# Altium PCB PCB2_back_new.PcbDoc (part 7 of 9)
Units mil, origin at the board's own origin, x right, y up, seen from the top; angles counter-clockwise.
Board outline 6299 x 3937 mil, 4 copper layers (TopLayer, GROUND, VCC, BottomLayer); 253 components, 421 nets, 2085 pads, 712 vias.
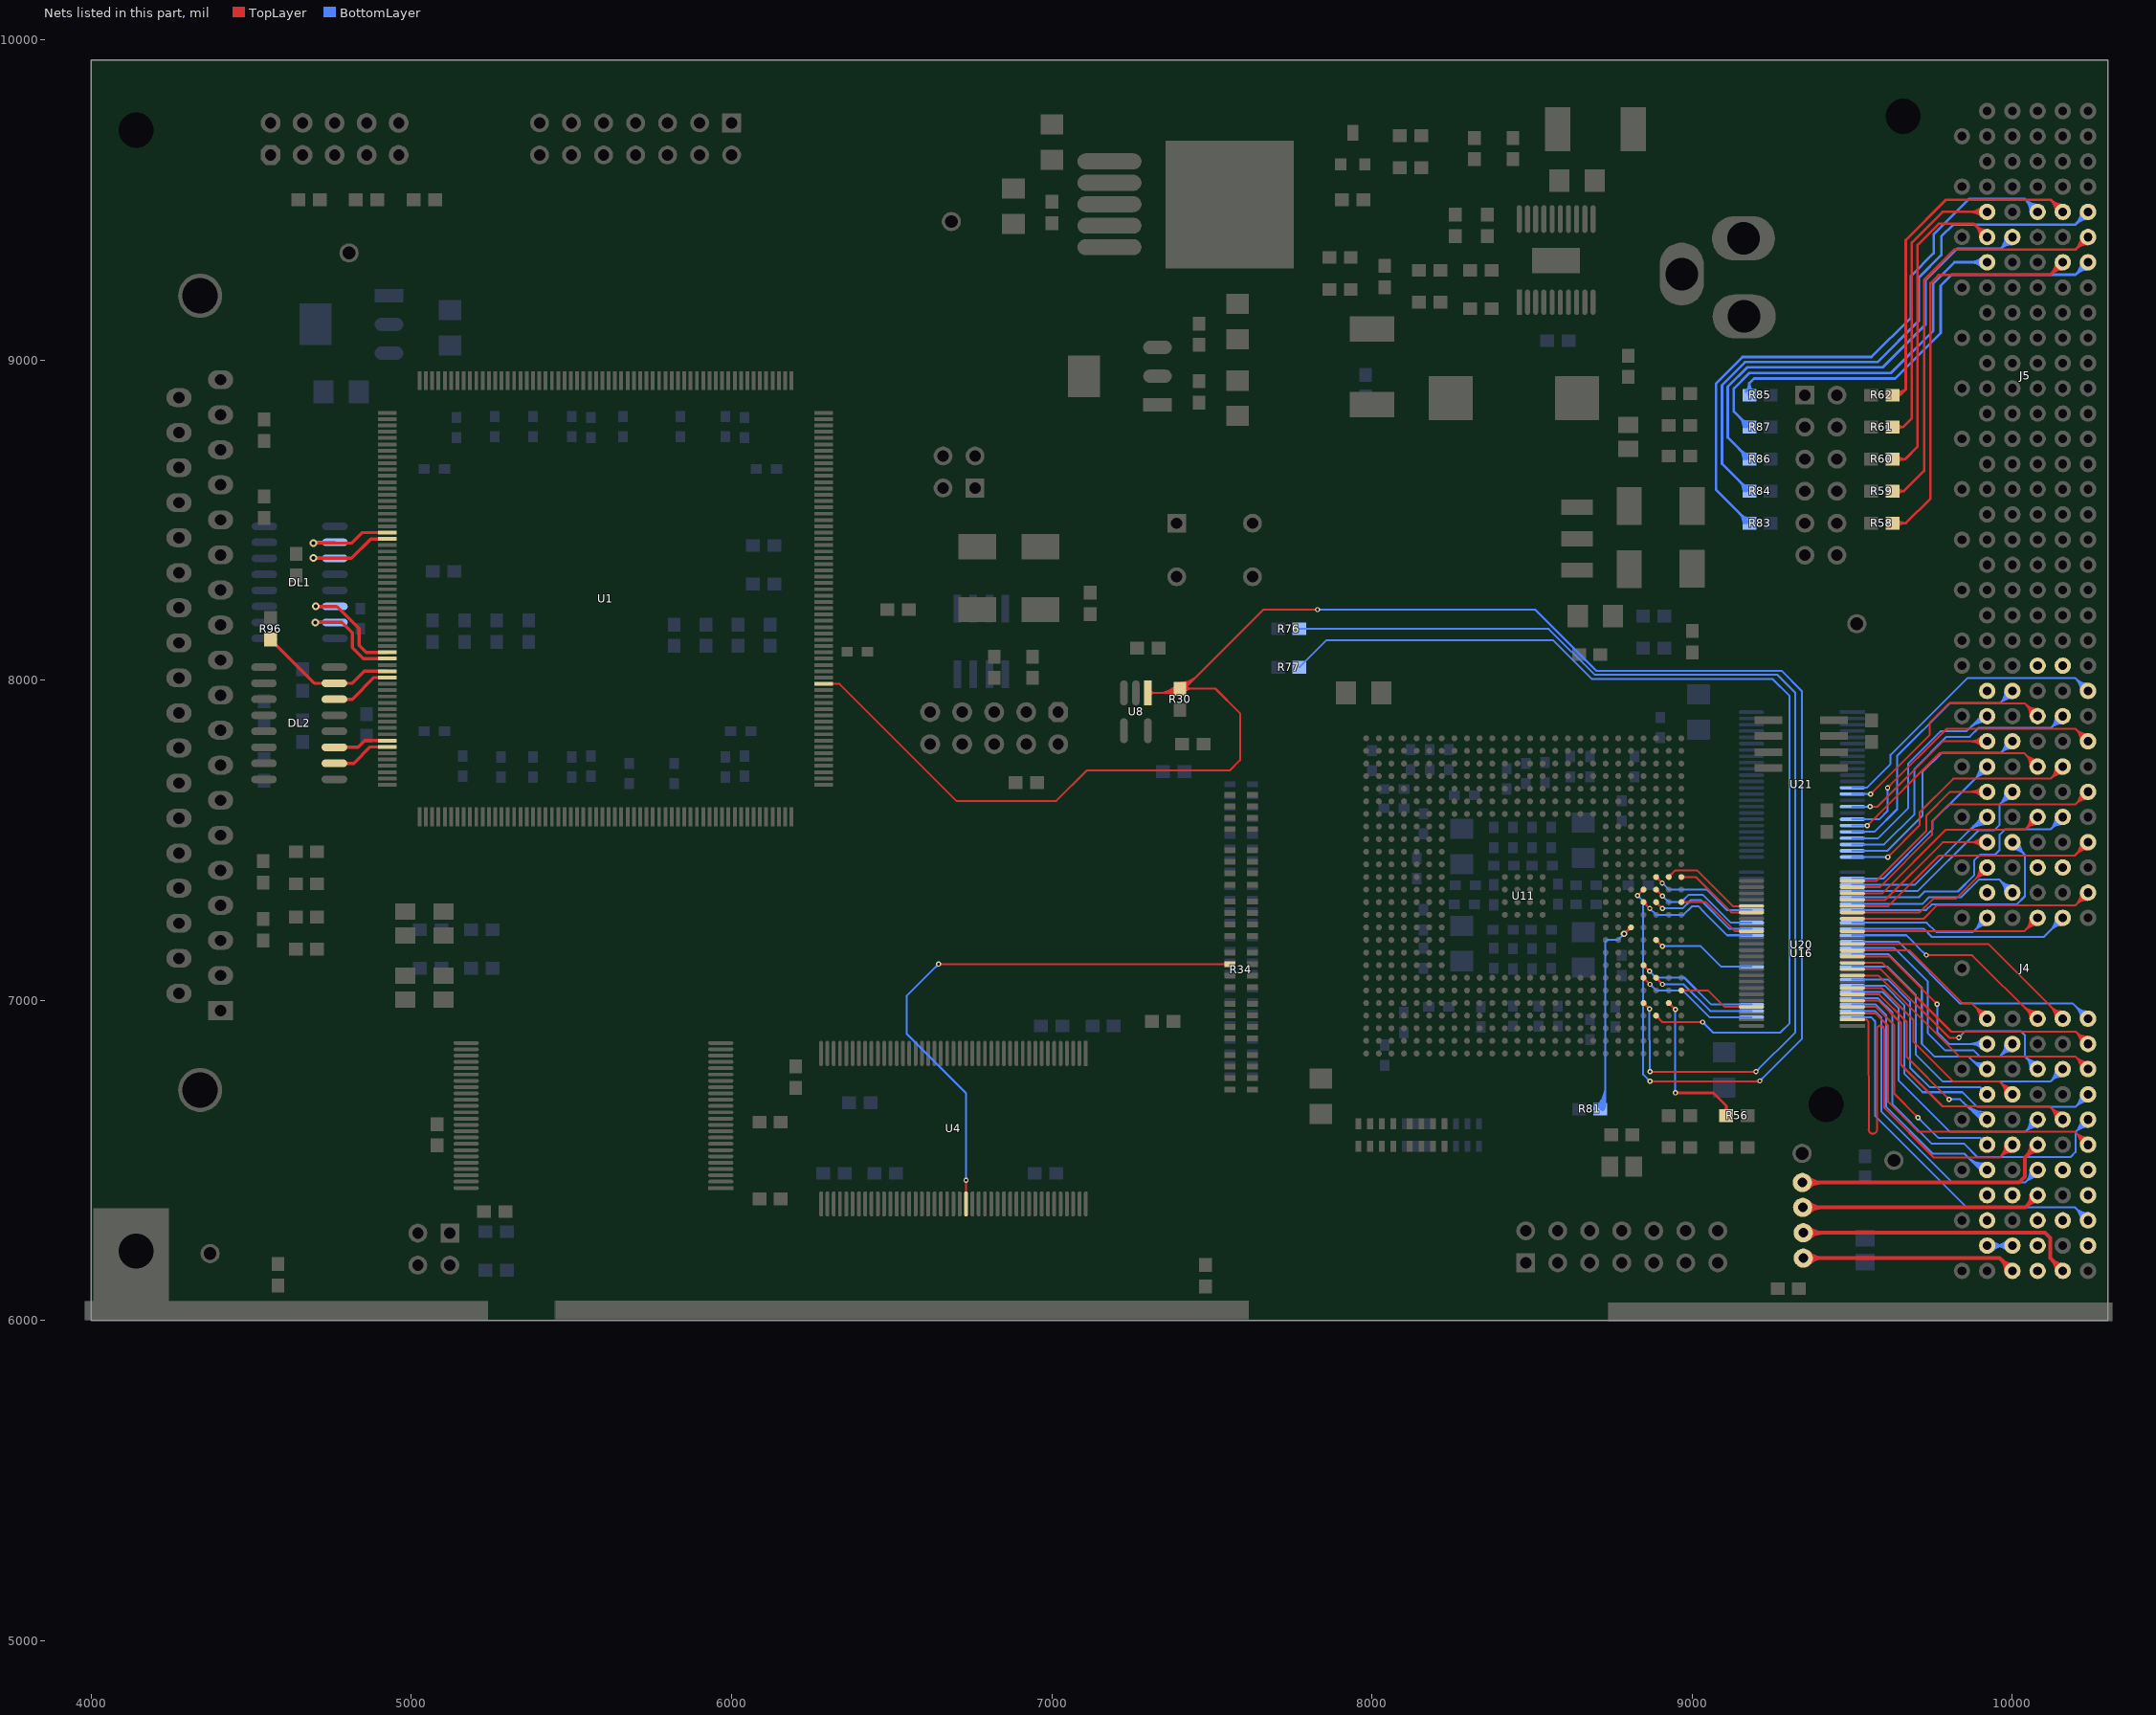
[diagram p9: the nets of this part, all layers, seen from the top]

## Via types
v1: diameter 16, hole 8, TopLayer to BottomLayer, 311 vias
v2: diameter 20, hole 10, TopLayer to BottomLayer, 202 vias
v3: diameter 24, hole 12, TopLayer to BottomLayer, 179 vias
v4: diameter 40, hole 20, TopLayer to BottomLayer, 12 vias
v5: diameter 30, hole 15, TopLayer to BottomLayer, 8 vias

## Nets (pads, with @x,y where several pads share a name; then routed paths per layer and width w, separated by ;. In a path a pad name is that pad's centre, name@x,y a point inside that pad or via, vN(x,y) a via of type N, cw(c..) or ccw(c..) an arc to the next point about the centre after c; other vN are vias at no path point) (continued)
P_EN: R56.1 U11.E2 | length 594.9
  TopLayer w6: U11.E2@8926.63,6985.23 cw(c8926.63,6970.14) 8937.3,6980.81 cw(c8947.98,6991.48) U11.E2@8932.88,6991.48 ; U11.E2@8926.63,6991.48 v1(8947,6971.11)
  TopLayer w8: v1(8947,6711) 9066,6711 9106.54,6670.46 ; v1@8949.83,6708.17 cw(c8956.66,6701.34) 8956.66,6711 cw(c8956.66,6720.66) v1@8949.83,6713.83 ; R56.1@9097.42,6652.77 ccw(c9084.79,6670.46) 9106.54,6670.46 ; R56.1@9106.54,6640 9106.54,6670.46 ; R56.1@9115.65,6652.77 cw(c9128.28,6670.46) 9106.54,6670.46
  BottomLayer w6: v1@8943.46,6714.54 ccw(c8934.93,6723.07) 8947,6723.07 ccw(c8959.07,6723.07) v1@8950.54,6714.54 ; v1(8947,6711) v1(8947,6971.11)
P_FRAME: U11.N4 U20.38 | length 435
  TopLayer w6: U11.N4@8847.89,7300.19 cw(c8847.89,7285.1) 8858.56,7295.77 cw(c8869.24,7306.44) U11.N4@8854.14,7306.44 ; U11.N4@8847.89,7306.44 v1(8867.33,7287)
  BottomLayer w6: v1(8867.33,7287) 8887.33,7267 8973,7267 8999,7293 9020,7293 9036,7277 ; 9035.5,7276.5 9108.85,7203.15 U20.38@9185.04,7203.15 ; U20.38@9149.4,7201.37 ccw(c9145.12,7197.09) 9145.12,7203.15 ccw(c9145.12,7209.21) U20.38@9149.4,7204.93
P_GNT: U11.H4 U20.27 | length 421.3
  TopLayer w6: U11.H4@8847.89,7103.34 cw(c8847.89,7088.25) 8858.56,7098.92 cw(c8869.24,7109.59) U11.H4@8854.14,7109.59 ; U11.H4@8847.89,7109.59 v1(8866.48,7091)
  BottomLayer w6: v1(8866.48,7091) 8886.48,7071 8975,7071 9059.39,6986.61 U20.27@9185.04,6986.61 ; U20.27@9149.4,6984.84 ccw(c9145.12,6980.55) 9145.12,6986.62 ccw(c9145.12,6992.68) U20.27@9149.4,6988.39
P_IDSEL: U11.K3 U20.33 | length 365.6
  TopLayer w6: U11.K3@8887.26,7182.08 cw(c8887.26,7166.99) 8897.93,7177.66 cw(c8908.61,7188.33) U11.K3@8893.51,7188.33 ; U11.K3@8887.26,7188.33 v1(8906.59,7169)
  BottomLayer w6: v1(8906.59,7169) 9026,7169 9090.27,7104.73 U20.33@9185.04,7104.73 ; U20.33@9149.4,7102.95 ccw(c9145.12,7098.66) 9145.12,7104.73 ccw(c9145.12,7110.79) U20.33@9149.4,7106.5
P_INTA: U11.G4 U20.25 | length 421.3
  TopLayer w6: U11.G4@8847.89,7063.97 cw(c8847.89,7048.88) 8858.56,7059.55 cw(c8869.24,7070.22) U11.G4@8854.14,7070.22 ; U11.G4@8847.89,7070.22 v1(8868.11,7050)
  BottomLayer w6: v1(8868.11,7050) 8887.11,7031 8970,7031 9053.75,6947.24 U20.25@9185.04,6947.24 ; U20.25@9149.4,6945.47 ccw(c9145.12,6941.18) 9145.12,6947.24 ccw(c9145.12,6953.31) U20.25@9149.4,6949.02
P_IRDY: U11.N1 U16.33 | length 290
  TopLayer w6: U11.N1@8966,7306.44 9042.56,7306.44 9133.73,7215.27 U16.33@9185.04,7215.27 ; U11.N1@8970.42,7302.02 cw(c8981.09,7291.35) 8981.09,7306.44 cw(c8981.09,7321.53) U11.N1@8970.42,7310.86 ; U16.33@9149.4,7213.5 ccw(c9145.12,7209.21) 9145.12,7215.28 ccw(c9145.12,7221.34) U16.33@9149.4,7217.05
P_PAR: U11.P3 U20.40 | length 392
  TopLayer w6: U11.P3@8887.26,7339.56 cw(c8887.26,7324.47) 8897.93,7335.14 cw(c8908.61,7345.81) U11.P3@8893.51,7345.81 ; U11.P3@8887.26,7345.81 v1(8907.07,7326)
  BottomLayer w6: v1(8907.07,7326) 8926.07,7307 8966,7307 8988,7329 9034,7329 9120.48,7242.52 U20.40@9185.04,7242.52 ; U20.40@9149.4,7240.74 ccw(c9145.12,7236.46) 9145.12,7242.52 ccw(c9145.12,7248.58) U20.40@9149.4,7244.3
P_PERR: U11.R1 U16.30 | length 298.2
  TopLayer w6: U11.R1@8966,7385.18 9010.82,7385.18 9121.67,7274.33 U16.30@9185.04,7274.33 ; U11.R1@8970.42,7380.76 cw(c8981.09,7370.09) 8981.09,7385.18 cw(c8981.09,7400.27) U11.R1@8970.42,7389.6 ; U16.30@9149.4,7272.55 ccw(c9145.12,7268.27) 9145.12,7274.33 ccw(c9145.12,7280.39) U16.30@9149.4,7276.11
P_REQ: U11.F1 U16.45 | length 273.7
  TopLayer w6: U11.F1@8966,7030.85 9049.15,7030.85 9100.94,6979.06 U16.45@9185.04,6979.06 ; U11.F1@8970.42,7026.43 cw(c8981.09,7015.76) 8981.09,7030.85 cw(c8981.09,7045.94) U11.F1@8970.42,7035.27 ; U16.45@9149.4,6977.28 ccw(c9145.12,6972.99) 9145.12,6979.06 ccw(c9145.12,6985.12) U16.45@9149.4,6980.83
P_RST: U11.G3 U20.26 | length 373.8
  TopLayer w6: U11.G3@8887.26,7063.97 cw(c8887.26,7048.88) 8897.93,7059.55 cw(c8908.61,7070.22) U11.G3@8893.51,7070.22 ; U11.G3@8887.26,7070.22 v1(8907.48,7050)
  BottomLayer w6: v1(8907.48,7050) 8973,7050 9056.07,6966.93 U20.26@9185.04,6966.93 ; U20.26@9149.4,6965.15 ccw(c9145.12,6960.87) 9145.12,6966.93 ccw(c9145.12,6972.99) U20.26@9149.4,6968.71
P_SERR: U11.R2 U16.29 | length 345.8
  TopLayer w6: U11.R2@8926.63,7385.18 8946.45,7405 9016,7405 9126.99,7294.02 U16.29@9185.04,7294.02 ; U11.R2@8926.63,7391.43 ccw(c8926.63,7406.53) 8937.3,7395.85 ccw(c8947.98,7385.18) U11.R2@8932.88,7385.18 ; U16.29@9149.4,7292.24 ccw(c9145.12,7287.95) 9145.12,7294.02 ccw(c9145.12,7300.08) U16.29@9149.4,7295.79
P_STOP: U11.R3 U20.42 | length 373.8
  TopLayer w6: U11.R3@8887.26,7378.93 cw(c8887.26,7363.84) 8897.93,7374.51 cw(c8908.61,7385.18) U11.R3@8893.51,7385.18 ; U11.R3@8887.26,7385.18 v1(8906.44,7366)
  BottomLayer w6: v1(8906.44,7366) 8926.44,7346 9044,7346 9108.11,7281.89 U20.42@9185.04,7281.89 ; U20.42@9149.4,7280.11 ccw(c9145.12,7275.83) 9145.12,7281.89 ccw(c9145.12,7287.95) U20.42@9149.4,7283.67
P_TRDY: U11.N3 U20.39 | length 387.2
  TopLayer w6: U11.N3@8887.26,7300.19 cw(c8887.26,7285.1) 8897.93,7295.77 cw(c8908.61,7306.44) U11.N3@8893.51,7306.44 ; U11.N3@8887.26,7306.44 v1(8906.7,7287)
  BottomLayer w6: v1(8906.7,7287) 8970,7287 8996,7313 9026,7313 9116.17,7222.84 U20.39@9185.04,7222.84 ; U20.39@9149.4,7221.06 ccw(c9145.12,7216.77) 9145.12,7222.84 ccw(c9145.12,7228.9) U20.39@9149.4,7224.61
PCI_EEAI: R81.1 U11.L5 | length 873.2
  TopLayer w8: v2(8787,7208) U11.L5@8808.52,7227.7 ; U11.L5@8803.27,7227.93 cw(c8790.61,7228.49) 8799.17,7219.14 cw(c8807.73,7209.79) U11.L5@8808.29,7222.45
  BottomLayer w6: R81.1@8703.63,6671.8 ccw(c8642.4,6733.03) 8729,6733.03 ; R81.1@8707.88,6667.56 ccw(c8656.88,6718.55) 8729,6718.55 ; R81.1@8712.12,6663.31 ccw(c8671.37,6704.06) 8729,6704.06 ; R81.1@8713.46,6660 8729,6675.54 8729,7183 8735,7189 8768,7189 v2(8787,7208) ; R81.1@8716.36,6659.07 ccw(c8685.85,6689.58) 8729,6689.58 ; R81.1@8720.61,6654.83 ccw(c8700.34,6675.09) R81.1@8729,6675.09
PXI_3.3V: J4.C6 pad.1@9344,6431 | length 984.1
  TopLayer w12: pad.1@9344,6431 10021,6431 10039,6449 10039,6509.14 J4.C6@10078.74,6548.88 ; pad.1@9360.97,6414.03 cw(c9401.94,6373.06) 9401.94,6431 cw(c9401.94,6488.94) pad.1@9360.97,6447.97 ; J4.C6@10059.15,6548.88 cw(c10011.85,6548.88) 10045.3,6515.44 cw(c10078.74,6482) J4.C6@10078.74,6529.29
PXI_+12V: J4.D1 pad.4 | length 834.8
  TopLayer w12: pad.4@9347,6195 9960.18,6195 J4.D1@10000,6155.18 ; pad.4@9363.97,6178.03 cw(c9404.94,6137.06) 9404.94,6195 cw(c9404.94,6252.94) pad.4@9363.97,6211.97 ; J4.D1@9980.41,6155.18 ccw(c9933.11,6155.18) 9966.56,6188.62 ccw(c10000,6222.07) J4.D1@10000,6174.77
PXI_-12V: J4.B1 pad.3 | length 1062.1
  TopLayer w12: pad.3@9347,6274 10102,6274 10118,6258 10118,6194.66 J4.B1@10157.48,6155.18 ; pad.3@9363.97,6257.03 cw(c9404.94,6216.06) 9404.94,6274 cw(c9404.94,6331.94) pad.3@9363.97,6290.97 ; J4.B1@10137.89,6155.18 ccw(c10090.59,6155.18) 10124.04,6188.62 ccw(c10157.48,6222.07) J4.B1@10157.48,6174.77
PXI_ACK64#: J4.E24
PXI_AD0: J4.D24 U21.20 | length 935.6
  BottomLayer w6: U21.20@9500,7525.98 9569,7525.98 9640,7596.98 9640,7763 9805,7928 9961.79,7928 ; U21.20@9535.63,7524.21 cw(c9539.92,7519.92) 9539.92,7525.99 cw(c9539.92,7532.05) U21.20@9535.63,7527.76 ; J4.D24@9977.41,7966.05 cw(c9924.1,7965.7) 9961.8,7928 ; J4.D24@9983.41,7966.09 cw(c9944.26,7965.83) 9971.94,7938.15 cw(c9999.63,7910.47) J4.D24@9999.89,7949.62 ; J4.D24@9999.85,7943.62 ccw(c9999.49,7890.31) 9961.8,7928 ; J4.D24@10000,7966.21 9961.79,7928
PXI_AD1: J4.A24 U21.13 | length 1069.8
  BottomLayer w6: U21.13@9500,7663.78 9544.78,7663.78 9619.67,7738.67 9619.67,7766.67 9860,8007 10195.43,8007 J4.A24@10236.22,7966.21 ; U21.13@9535.63,7662 cw(c9539.92,7657.72) 9539.92,7663.78 cw(c9539.92,7669.84) U21.13@9535.63,7665.56 ; J4.A24@10213.63,7966.21 ccw(c10159.09,7966.21) 10197.66,8004.77 ccw(c10236.22,8043.33) J4.A24@10236.22,7988.8 ; J4.A24@10219.63,7966.21 ccw(c10179.58,7966.21) 10207.9,7994.53 ccw(c10236.22,8022.85) J4.A24@10236.22,7982.8
PXI_AD2: J4.E23 U21.21 | length 871.5
  BottomLayer w6: U21.21@9500,7506.3 9581,7506.3 9674,7599.3 9674,7738 9777,7841 9857,7841 9903.47,7887.47 J4.E23@9921.26,7887.47 ; U21.21@9535.63,7504.52 cw(c9539.92,7500.24) 9539.92,7506.3 cw(c9539.92,7512.36) U21.21@9535.63,7508.08 ; 9862.56,7846.56 cw(c9921.26,7787.86) J4.E23@9921.26,7870.87 ; 9872.8,7856.8 cw(c9921.26,7808.35) J4.E23@9921.26,7876.87 ; 9883.05,7867.05 cw(c9921.26,7828.83) J4.E23@9921.26,7882.87 ; 9893.29,7877.29 cw(c9921.26,7849.32) J4.E23@9921.26,7888.87 ; 9895.28,7879.28 ccw(c9887.09,7887.47) J4.E23@9898.67,7887.47
PXI_AD3: J4.C23 U21.14 | length 931.2
  TopLayer w6: v1(9557.09,7644.1) 9741,7828 9741,7867 9801,7927 10039.2,7927 J4.C23@10078.74,7887.47 ; v1@9557.09,7649.1 ccw(c9557.09,7661.17) 9565.63,7652.63 ccw(c9574.17,7644.1) v1@9562.1,7644.1 ; J4.C23@10056.15,7887.47 ccw(c10001.61,7887.47) 10040.18,7926.03 ccw(c10078.74,7964.59) J4.C23@10078.74,7910.06 ; J4.C23@10062.15,7887.47 ccw(c10022.1,7887.47) 10050.42,7915.79 ccw(c10078.74,7944.11) J4.C23@10078.74,7904.06
  BottomLayer w6: U21.14@9500,7644.1 v1(9557.09,7644.1) ; U21.14@9535.63,7642.32 cw(c9539.92,7638.03) 9539.92,7644.1 cw(c9539.92,7650.16) U21.14@9535.63,7645.87 ; v1@9553.56,7640.56 ccw(c9545.02,7632.02) 9545.02,7644.1 ccw(c9545.02,7656.17) v1@9553.56,7647.63
PXI_AD4: J4.B23 U21.22 | length 1052.1
  BottomLayer w6: U21.22@9500,7486.61 9599,7486.61 9694,7581.61 9694,7723 9793.9,7822.9 9866.9,7822.9 9895,7851 10121.02,7851 ; U21.22@9535.63,7484.84 cw(c9539.92,7480.55) 9539.92,7486.62 cw(c9539.92,7492.68) U21.22@9535.63,7488.39 ; J4.B23@10134.91,7886.55 cw(c10087.39,7884.63) 10121.02,7851 ; J4.B23@10140.9,7886.79 cw(c10106,7885.38) 10130.7,7860.69 cw(c10155.4,7835.99) J4.B23@10156.81,7870.89 ; J4.B23@10156.57,7864.89 ccw(c10154.65,7817.37) 10121.02,7851 ; J4.B23@10157.48,7887.47 10121.02,7851
PXI_AD5: J4.E22 U21.16 | length 722
  TopLayer w6: v1(9555.73,7604.73) 9578.73,7604.73 9782.66,7808.66 9921.2,7808.66 J4.E22@9921.26,7808.72 ; v1@9559.26,7601.19 cw(c9567.8,7592.65) 9567.8,7604.73 cw(c9567.8,7616.8) v1@9559.26,7608.26 ; 9866.57,7808.66 ccw(c9866.57,7863.42) J4.E22@9905.29,7824.7 ; 9866.87,7808.66 cw(c9866.87,7754.34) J4.E22@9905.29,7792.75 ; 9881.05,7808.66 ccw(c9881.05,7848.93) J4.E22@9909.53,7820.46 ; 9881.36,7808.66 cw(c9881.36,7768.82) J4.E22@9909.53,7796.99 ; 9895.54,7808.66 ccw(c9895.54,7834.44) J4.E22@9913.77,7816.21
  BottomLayer w6: U21.16@9500,7604.73 v1(9555.73,7604.73) ; U21.16@9535.63,7602.95 cw(c9539.92,7598.66) 9539.92,7604.73 cw(c9539.92,7610.79) U21.16@9535.63,7606.5 ; v1@9552.19,7601.19 ccw(c9543.65,7592.65) 9543.65,7604.73 ccw(c9543.65,7616.8) v1@9552.19,7608.26
PXI_AD6: J4.D22 U21.23 | length 863.2
  BottomLayer w6: U21.23@9500,7466.93 9610,7466.93 9719,7575.93 9719,7713 9779,7773 9964.28,7773 ; U21.23@9535.63,7465.15 cw(c9539.92,7460.87) 9539.92,7466.93 cw(c9539.92,7472.99) U21.23@9535.63,7468.71 ; J4.D22@9977.44,7807.47 cw(c9932.32,7804.96) 9964.28,7773 ; J4.D22@9983.43,7807.8 cw(c9950.3,7805.96) 9973.76,7782.49 cw(c9997.23,7759.02) J4.D22@9999.08,7792.16 ; J4.D22@9998.74,7786.17 ccw(c9996.23,7741.05) 9964.28,7773 ; J4.D22@10000,7808.72 9964.28,7773
PXI_AD7: J4.A22 U21.18 | length 1107.8
  TopLayer w6: v1(9610,7663) 9795,7848 10196.95,7848 J4.A22@10236.22,7808.72 ; v1@9610,7668 ccw(c9610,7680.07) 9618.54,7671.54 ccw(c9627.07,7663) v1@9615,7663 ; J4.A22@10213.63,7808.72 ccw(c10159.09,7808.72) 10197.66,7847.29 ccw(c10236.22,7885.85) J4.A22@10236.22,7831.32 ; J4.A22@10219.63,7808.72 ccw(c10179.58,7808.72) 10207.9,7837.05 ccw(c10236.22,7865.37) J4.A22@10236.22,7825.32
  BottomLayer w6: U21.18@9500,7565.35 9584.35,7565.35 9610,7591 v1(9610,7663) ; U21.18@9535.63,7563.58 cw(c9539.92,7559.29) 9539.92,7565.36 cw(c9539.92,7571.42) U21.18@9535.63,7567.13 ; v1@9606.46,7659.46 cw(c9597.93,7650.93) 9610,7650.93 cw(c9622.07,7650.93) v1@9613.54,7659.46
PXI_AD8: J4.C21 U21.19 | length 885.9
  TopLayer w6: v1(9546.67,7545.67) 9773,7772 10036.72,7772 J4.C21@10078.74,7729.98 ; v1@9546.67,7550.67 ccw(c9546.67,7562.74) 9555.21,7554.21 ccw(c9563.74,7545.67) v1@9551.67,7545.67 ; J4.C21@10056.15,7729.98 ccw(c10001.61,7729.98) 10040.18,7768.55 ccw(c10078.74,7807.11) J4.C21@10078.74,7752.58 ; J4.C21@10062.15,7729.98 ccw(c10022.1,7729.98) 10050.42,7758.31 ccw(c10078.74,7786.63) J4.C21@10078.74,7746.58
  BottomLayer w6: U21.19@9500,7545.67 v1(9546.67,7545.67) ; U21.19@9535.63,7543.89 cw(c9539.92,7539.61) 9539.92,7545.67 cw(c9539.92,7551.73) U21.19@9535.63,7547.45 ; v1@9543.13,7542.13 ccw(c9534.6,7533.6) 9534.6,7545.67 ccw(c9534.6,7557.74) v1@9543.13,7549.21
PXI_AD9: J4.B21 U21.24 | length 991.2
  TopLayer w6: v1(9611.25,7447.24) 9710.28,7546.28 9710.28,7587.28 9815,7692 10119.5,7692 ; v1@9611.25,7452.24 ccw(c9611.25,7464.32) 9619.78,7455.78 ccw(c9628.32,7447.24) v1@9616.25,7447.24 ; J4.B21@10134.89,7729.74 cw(c10082.33,7729.17) 10119.5,7692 ; J4.B21@10140.89,7729.81 cw(c10102.29,7729.39) 10129.59,7702.09 cw(c10156.88,7674.79) J4.B21@10157.3,7713.4 ; J4.B21@10157.24,7707.4 ccw(c10156.67,7654.83) 10119.5,7692 ; J4.B21@10157.48,7729.98 10119.5,7692
  BottomLayer w6: U21.24@9500,7447.24 v1(9611.25,7447.24) ; U21.24@9535.63,7445.47 cw(c9539.92,7441.18) 9539.92,7447.24 cw(c9539.92,7453.31) U21.24@9535.63,7449.02 ; v1@9607.71,7443.71 ccw(c9599.17,7435.17) 9599.17,7447.24 ccw(c9599.17,7459.32) v1@9607.71,7450.78
PXI_AD10: J4.E20 U16.24 | length 743.1
  TopLayer w6: U16.24@9500,7372.76 9574.75,7372.76 9731.25,7529.25 9731.25,7577.25 9805.18,7651.18 9921.2,7651.18 J4.E20@9921.26,7651.24 ; U16.24@9535.63,7370.98 cw(c9539.92,7366.69) 9539.92,7372.76 cw(c9539.92,7378.82) U16.24@9535.63,7374.53 ; 9866.57,7651.18 ccw(c9866.57,7705.93) J4.E20@9905.29,7667.22 ; 9866.87,7651.18 cw(c9866.87,7596.86) J4.E20@9905.29,7635.27 ; 9881.05,7651.18 ccw(c9881.05,7691.45) J4.E20@9909.53,7662.98 ; 9881.36,7651.18 cw(c9881.36,7611.34) J4.E20@9909.53,7639.51 ; 9895.54,7651.18 ccw(c9895.54,7676.96) J4.E20@9913.77,7658.73
PXI_AD11: J4.D20 U20.4 | length 823.7
  BottomLayer w6: U20.4@9500,7340.94 9703.94,7340.94 9894,7531 9943,7531 9960,7548 9960,7611.24 J4.D20@10000,7651.24 ; U20.4@9535.63,7339.17 cw(c9539.92,7334.88) 9539.92,7340.95 cw(c9539.92,7347.01) U20.4@9535.63,7342.72 ; J4.D20@9977.41,7651.24 cw(c9922.87,7651.24) 9961.44,7612.68 cw(c10000,7574.12) J4.D20@10000,7628.65 ; J4.D20@9983.41,7651.24 cw(c9943.36,7651.24) 9971.68,7622.92 cw(c10000,7594.6) J4.D20@10000,7634.65
PXI_AD12: J4.A20 U16.23 | length 1042.4
  TopLayer w6: U16.23@9500,7353.07 9585.07,7353.07 9748.62,7516.62 9748.62,7558.62 9802,7612 10196.98,7612 J4.A20@10236.22,7651.24 ; U16.23@9535.63,7351.29 cw(c9539.92,7347.01) 9539.92,7353.07 cw(c9539.92,7359.13) U16.23@9535.63,7354.85 ; J4.A20@10213.63,7651.24 cw(c10159.09,7651.24) 10197.66,7612.68 cw(c10236.22,7574.12) J4.A20@10236.22,7628.65 ; J4.A20@10219.63,7651.24 cw(c10179.58,7651.24) 10207.9,7622.92 cw(c10236.22,7594.6) J4.A20@10236.22,7634.65
PXI_AD13: J4.E19 U20.3 | length 748.4
  BottomLayer w6: U20.3@9500,7360.63 9694.63,7360.63 9906.5,7572.5 J4.E19@9921.26,7572.5 ; U20.3@9535.63,7358.85 cw(c9539.92,7354.57) 9539.92,7360.63 cw(c9539.92,7366.69) U20.3@9535.63,7362.41 ; 9857.51,7523.51 cw(c9921.26,7459.75) J4.E19@9921.26,7549.91 ; 9867.75,7533.75 cw(c9921.26,7480.24) J4.E19@9921.26,7555.91 ; 9877.99,7543.99 cw(c9921.26,7500.72) J4.E19@9921.26,7561.91 ; 9888.23,7554.23 cw(c9921.26,7521.21) J4.E19@9921.26,7567.91 ; 9893.13,7559.13 ccw(c9879.75,7572.5) J4.E19@9898.67,7572.5
PXI_AD14: J4.C19 U16.22 | length 835.9
  TopLayer w6: U16.22@9500,7333.39 9592.39,7333.39 9791,7532 10038.24,7532 J4.C19@10078.74,7572.5 ; U16.22@9535.63,7331.61 cw(c9539.92,7327.32) 9539.92,7333.39 cw(c9539.92,7339.45) U16.22@9535.63,7335.16 ; J4.C19@10056.15,7572.5 cw(c10001.61,7572.5) 10040.18,7533.94 cw(c10078.74,7495.38) J4.C19@10078.74,7549.91 ; J4.C19@10062.15,7572.5 cw(c10022.1,7572.5) 10050.42,7544.18 cw(c10078.74,7515.86) J4.C19@10078.74,7555.91
PXI_AD15: J4.B19 U20.5 | length 973.8
  BottomLayer w6: U20.5@9500,7321.26 9707.37,7321.26 9726,7339.89 9829.89,7339.89 9880,7390 9880,7436 9899,7455 9945,7455 9960,7470 9960,7517 9977,7534 10118.98,7534 ; U20.5@9535.63,7319.48 cw(c9539.92,7315.2) 9539.92,7321.26 cw(c9539.92,7327.32) U20.5@9535.63,7323.04 ; J4.B19@10134.89,7572.48 cw(c10080.57,7572.42) 10118.98,7534 ; J4.B19@10140.89,7572.49 cw(c10100.99,7572.44) 10129.2,7544.23 cw(c10157.42,7516.02) J4.B19@10157.46,7555.91 ; J4.B19@10157.45,7549.91 ccw(c10157.39,7495.59) 10118.98,7534 ; J4.B19@10157.48,7572.5 10118.98,7534
PXI_AD16: J4.C11 U20.11 | length 914.8
  TopLayer w6: v1(9731,7141) 9874,7141 10072.42,6942.58 J4.C11@10078.74,6942.58 ; v1@9734.54,7137.46 cw(c9743.07,7128.93) 9743.07,7141 cw(c9743.07,7153.07) v1@9734.54,7144.54 ; 10029.38,6985.62 ccw(c10078.74,7034.98) J4.C11@10078.74,6965.17 ; 10039.62,6975.38 ccw(c10078.74,7014.49) J4.C11@10078.74,6959.17 ; 10044.65,6970.35 cw(c10016.88,6942.58) J4.C11@10056.15,6942.58 ; 10049.87,6965.13 ccw(c10078.74,6994) J4.C11@10078.74,6953.17 ; 10054.89,6960.11 cw(c10037.36,6942.58) J4.C11@10062.15,6942.58
  BottomLayer w6: U20.11@9500,7203.15 9668.85,7203.15 v1(9731,7141) ; U20.11@9535.63,7201.37 cw(c9539.92,7197.09) 9539.92,7203.15 cw(c9539.92,7209.21) U20.11@9535.63,7204.93 ; v1@9726,7141 ccw(c9713.93,7141) 9722.46,7149.54 ccw(c9731,7158.07) v1@9731,7146
PXI_AD17: J4.B11 U16.14 | length 912.2
  TopLayer w6: U16.14@9500,7175.9 9924.16,7175.9 J4.B11@10157.48,6942.58 ; U16.14@9535.63,7174.13 cw(c9539.92,7169.84) 9539.92,7175.91 cw(c9539.92,7181.97) U16.14@9535.63,7177.68 ; J4.B11@10134.89,6942.58 ccw(c10080.35,6942.58) 10118.92,6981.15 ccw(c10157.48,7019.71) J4.B11@10157.48,6965.17 ; J4.B11@10140.89,6942.58 ccw(c10100.84,6942.58) 10129.16,6970.9 ccw(c10157.48,6999.23) J4.B11@10157.48,6959.17
PXI_AD18: J4.A11 U20.12 | length 994.1
  BottomLayer w6: U20.12@9500,7183.47 9643.53,7183.47 9837,6990 10188.8,6990 J4.A11@10236.22,6942.58 ; U20.12@9535.63,7181.69 cw(c9539.92,7177.4) 9539.92,7183.47 cw(c9539.92,7189.53) U20.12@9535.63,7185.24 ; J4.A11@10213.63,6942.58 ccw(c10159.09,6942.58) 10197.66,6981.15 ccw(c10236.22,7019.71) J4.A11@10236.22,6965.17 ; J4.A11@10219.63,6942.58 ccw(c10179.58,6942.58) 10207.9,6970.9 ccw(c10236.22,6999.23) J4.A11@10236.22,6959.17
PXI_AD19: J4.E10 U16.12 | length 801.5
  TopLayer w6: U16.12@9500,7136.53 9616.47,7136.53 v1(9765,6988) ; U16.12@9535.63,7134.76 cw(c9539.92,7130.47) 9539.92,7136.53 cw(c9539.92,7142.6) U16.12@9535.63,7138.31 ; v1@9760,6988 ccw(c9747.93,6988) 9756.46,6996.54 ccw(c9765,7005.07) v1@9765,6993
  BottomLayer w6: v1@9761.46,6984.46 cw(c9752.93,6975.93) 9765,6975.93 cw(c9777.07,6975.93) v1@9768.54,6984.46 ; v1(9765,6988) 9765,6901 9802.22,6863.78 9921.2,6863.78 J4.E10@9921.26,6863.84 ; 9866.57,6863.78 ccw(c9866.57,6918.53) J4.E10@9905.29,6879.82 ; 9866.87,6863.78 cw(c9866.87,6809.46) J4.E10@9905.29,6847.87 ; 9881.05,6863.78 ccw(c9881.05,6904.05) J4.E10@9909.53,6875.57 ; 9881.36,6863.78 cw(c9881.36,6823.94) J4.E10@9909.53,6852.11 ; 9895.54,6863.78 ccw(c9895.54,6889.56) J4.E10@9913.77,6871.33
PXI_AD20: J4.D10 U20.13 | length 909.4
  BottomLayer w6: U20.13@9500,7163.78 9630.22,7163.78 9736,7058 9736,6897.39 9789,6844.39 9878.61,6844.39 9899,6824 9960.16,6824 J4.D10@10000,6863.84 ; U20.13@9535.63,7162 cw(c9539.92,7157.72) 9539.92,7163.78 cw(c9539.92,7169.84) U20.13@9535.63,7165.56 ; J4.D10@9977.41,6863.84 cw(c9922.87,6863.84) 9961.44,6825.28 cw(c10000,6786.71) J4.D10@10000,6841.25 ; J4.D10@9983.41,6863.84 cw(c9943.36,6863.84) 9971.68,6835.52 cw(c10000,6807.2) J4.D10@10000,6847.25
PXI_AD21: J4.A10 U16.11 | length 996.7
  TopLayer w6: U16.11@9500,7116.85 9594.15,7116.85 9809,6902 10198.06,6902 ; U16.11@9535.63,7115.07 cw(c9539.92,7110.79) 9539.92,7116.85 cw(c9539.92,7122.91) U16.11@9535.63,7118.63 ; J4.A10@10213.63,6864.01 ccw(c10160.48,6864.41) 10198.06,6902 ; J4.A10@10219.63,6863.97 ccw(c10180.6,6864.26) 10208.2,6891.86 ccw(c10235.8,6919.47) J4.A10@10236.09,6880.43 ; J4.A10@10236.05,6886.43 cw(c10235.65,6939.58) 10198.06,6902 ; J4.A10@10236.22,6863.84 10198.06,6902
PXI_AD22: J4.E9 U20.14 | length 829.1
  BottomLayer w6: U20.14@9500,7144.1 9612.91,7144.1 9717,7040 9717,6864 9757,6824 9863,6824 9901.9,6785.1 J4.E9@9921.26,6785.1 ; U20.14@9535.63,7142.32 cw(c9539.92,7138.03) 9539.92,7144.1 cw(c9539.92,7150.16) U20.14@9535.63,7145.87 ; 9872.68,6814.32 ccw(c9899.02,6840.66) J4.E9@9912.86,6806.07 ; 9879.11,6807.89 ccw(c9902.7,6831.47) J4.E9@9915.09,6800.5 ; 9885.55,6801.45 ccw(c9906.38,6822.28) J4.E9@9917.32,6794.93 ; 9891.98,6795.02 ccw(c9910.05,6813.1) J4.E9@9919.55,6789.36
PXI_AD23: J4.C9 U16.10 | length 959.7
  TopLayer w6: U16.10@9500,7097.16 9588.83,7097.16 9803,6883 v1(9833,6883) ; U16.10@9535.63,7095.39 cw(c9539.92,7091.1) 9539.92,7097.16 cw(c9539.92,7103.23) U16.10@9535.63,7098.94 ; v1@9829.46,6879.46 ccw(c9820.93,6870.93) 9820.93,6883 ccw(c9820.93,6895.07) v1@9829.46,6886.54
  BottomLayer w6: v1@9832.87,6888 ccw(c9832.56,6900.07) 9841.31,6891.75 ccw(c9850.07,6883.44) v1@9838,6883.13 ; v1(9833,6883) 9852,6903 10027,6903 10039,6891 10039,6824.84 J4.C9@10078.74,6785.1 ; J4.C9@10056.15,6785.1 ccw(c10001.61,6785.1) 10040.18,6823.67 ccw(c10078.74,6862.23) J4.C9@10078.74,6807.69 ; J4.C9@10062.15,6785.1 ccw(c10022.1,6785.1) 10050.42,6813.42 ccw(c10078.74,6841.75) J4.C9@10078.74,6801.69
PXI_AD24: J4.E8 U20.18 | length 724.1
  BottomLayer w6: U20.18@9500,7065.35 9610.65,7065.35 9680,6996 9680,6790 9742,6728 9899.62,6728 ; U20.18@9535.63,7063.58 cw(c9539.92,7059.29) 9539.92,7065.36 cw(c9539.92,7071.42) U20.18@9535.63,7067.13 ; J4.E8@9901.29,6716.92 ccw(c9892.96,6721.33) 9899.62,6728 ; J4.E8@9910.7,6726.33 cw(c9906.29,6734.67) 9899.62,6728 ; J4.E8@9921.26,6706.36 9899.62,6728
PXI_AD25: J4.D8 U16.7 | length 835.4
  TopLayer w6: U16.7@9500,7038.11 9590.89,7038.11 9691.07,6937.93 9691.07,6869.93 9814,6747 9959.36,6747 J4.D8@10000,6706.36 ; U16.7@9535.63,7036.33 cw(c9539.92,7032.05) 9539.92,7038.11 cw(c9539.92,7044.17) U16.7@9535.63,7039.89 ; J4.D8@9977.41,6706.36 ccw(c9922.87,6706.36) 9961.44,6744.93 ccw(c10000,6783.49) J4.D8@10000,6728.95 ; J4.D8@9983.41,6706.36 ccw(c9943.36,6706.36) 9971.68,6734.68 ccw(c10000,6763.01) J4.D8@10000,6722.95
PXI_AD26: J4.A8 U20.19 | length 1190.8
  BottomLayer w6: U20.19@9500,7045.67 9601.33,7045.67 9663,6984 9663,6770 9720,6713 9844,6713 9889,6668 10197.86,6668 ; U20.19@9535.63,7043.89 cw(c9539.92,7039.61) 9539.92,7045.67 cw(c9539.92,7051.73) U20.19@9535.63,7047.45 ; J4.A8@10213.63,6706.28 cw(c10159.79,6706.07) 10197.86,6668 ; J4.A8@10219.63,6706.3 cw(c10180.09,6706.15) 10208.05,6678.19 cw(c10236.01,6650.23) J4.A8@10236.16,6689.77 ; J4.A8@10236.14,6683.77 ccw(c10235.93,6629.93) 10197.86,6668 ; J4.A8@10236.22,6706.36 10197.86,6668
PXI_AD27: J4.E7 U16.6 | length 993.5
  TopLayer w6: U16.6@9500,7018.43 9584.58,7018.43 9670,6933 9670,6823 v1(9802,6691) ; U16.6@9535.63,7016.65 cw(c9539.92,7012.36) 9539.92,7018.43 cw(c9539.92,7024.49) U16.6@9535.63,7020.2 ; v1@9797,6691 ccw(c9784.93,6691) 9793.46,6699.54 ccw(c9802,6708.07) v1@9802,6696
  BottomLayer w6: v1@9802,6689 v1@9804,6689 ; v1(9802,6691) 9837,6691 9900.38,6627.62 J4.E7@9921.26,6627.62 ; v1@9805.54,6687.46 cw(c9814.07,6678.93) 9814.07,6691 cw(c9814.07,6703.07) v1@9805.54,6694.54 ; 9847.44,6680.56 ccw(c9920.7,6753.81) J4.E7@9921.16,6650.21 ; 9857.62,6670.38 ccw(c9920.79,6733.54) J4.E7@9921.19,6644.21 ; 9867.8,6660.2 ccw(c9920.88,6713.28) J4.E7@9921.21,6638.21 ; 9877.98,6650.02 ccw(c9920.97,6693.01) J4.E7@9921.24,6632.21 ; 9888.16,6639.84 ccw(c9921.06,6672.74) J4.E7@9921.27,6626.21
PXI_AD28: J4.C7 U20.20 | length 1066.2
  BottomLayer w6: U20.20@9500,7025.98 9594.01,7025.98 9645,6975 9645,6749 9805,6589 10040.12,6589 J4.C7@10078.74,6627.62 ; U20.20@9535.63,7024.21 cw(c9539.92,7019.92) 9539.92,7025.99 cw(c9539.92,7032.05) U20.20@9535.63,7027.76 ; J4.C7@10056.15,6627.62 cw(c10001.61,6627.62) 10040.18,6589.06 cw(c10078.74,6550.49) J4.C7@10078.74,6605.03 ; J4.C7@10062.15,6627.62 cw(c10022.1,6627.62) 10050.42,6599.3 cw(c10078.74,6570.98) J4.C7@10078.74,6611.03
PXI_AD29: J4.B7 U16.5 | length 1045.5
  TopLayer w6: U16.5@9500,6998.74 9582.26,6998.74 9652,6929 9652,6799 9782,6669 10116.1,6669 J4.B7@10157.48,6627.62 ; U16.5@9535.63,6996.96 cw(c9539.92,6992.68) 9539.92,6998.74 cw(c9539.92,7004.8) U16.5@9535.63,7000.52 ; J4.B7@10134.89,6627.62 ccw(c10080.35,6627.62) 10118.92,6666.19 ccw(c10157.48,6704.75) J4.B7@10157.48,6650.21 ; J4.B7@10140.89,6627.62 ccw(c10100.84,6627.62) 10129.16,6655.94 ccw(c10157.48,6684.27) J4.B7@10157.48,6644.21
PXI_AD30: J4.A7 U20.21 | length 1353.3
  BottomLayer w6: U20.21@9500,7006.3 9580.7,7006.3 9625,6962 9625,6675 9747,6553 9848,6553 9891,6510 10181,6510 10197,6526 10197,6588.4 J4.A7@10236.22,6627.62 ; U20.21@9535.63,7004.52 cw(c9539.92,7000.24) 9539.92,7006.3 cw(c9539.92,7012.36) U20.21@9535.63,7008.08 ; J4.A7@10213.63,6627.62 cw(c10159.09,6627.62) 10197.66,6589.06 cw(c10236.22,6550.49) J4.A7@10236.22,6605.03 ; J4.A7@10219.63,6627.62 cw(c10179.58,6627.62) 10207.9,6599.3 cw(c10236.22,6570.98) J4.A7@10236.22,6611.03
PXI_AD31: J4.E6 U16.4 | length 798.2
  TopLayer w6: U16.4@9500,6979.06 9573.94,6979.06 9631,6922 9631,6708 v1(9705,6634) ; U16.4@9535.63,6977.28 cw(c9539.92,6972.99) 9539.92,6979.06 cw(c9539.92,6985.12) U16.4@9535.63,6980.83 ; v1@9700,6634 ccw(c9687.93,6634) 9696.46,6642.54 ccw(c9705,6651.07) v1@9705,6639
  BottomLayer w6: v1@9705,6629 cw(c9705,6616.93) 9713.54,6625.46 cw(c9722.07,6634) v1@9710,6634 ; v1(9705,6634) 9768,6571 9899.14,6571 ; J4.E6@9901.07,6559.02 ccw(c9891.82,6563.67) 9899.14,6571 ; J4.E6@9911.12,6569.07 cw(c9906.47,6578.32) 9899.14,6571 ; J4.E6@9921.26,6548.88 9899.14,6571
PXI_BRSVP1A5: J4.A5
PXI_BRSVP1B5: J4.B5
PXI_C/BE0#: J4.E21 U20.2 | length 739.1
  BottomLayer w6: U20.2@9500,7380.31 9597,7380.31 9751,7534.31 9751,7559.72 9828.35,7637.08 J4.E21@9921.26,7729.98 ; U20.2@9535.63,7378.54 cw(c9539.92,7374.25) 9539.92,7380.32 cw(c9539.92,7386.38) U20.2@9535.63,7382.09 ; J4.E21@9898.67,7729.98 cw(c9844.13,7729.98) 9882.7,7691.42 cw(c9921.26,7652.86) J4.E21@9921.26,7707.39 ; J4.E21@9904.67,7729.98 cw(c9864.62,7729.98) 9892.94,7701.66 cw(c9921.26,7673.34) J4.E21@9921.26,7713.39
PXI_C/BE1#: J4.E18 U16.21 | length 663.7
  TopLayer w6: U16.21@9500,7313.7 9602.7,7313.7 9782.7,7493.7 9892.7,7493.7 ; U16.21@9535.63,7311.92 cw(c9539.92,7307.64) 9539.92,7313.7 cw(c9539.92,7319.76) U16.21@9535.63,7315.48 ; 9866.57,7493.7 ccw(c9866.57,7548.45) J4.E18@9905.29,7509.74 ; 9866.87,7493.7 cw(c9866.87,7439.38) J4.E18@9905.29,7477.79 ; 9881.05,7493.7 ccw(c9881.05,7533.97) J4.E18@9909.53,7505.5 ; 9881.36,7493.7 cw(c9881.36,7453.86) J4.E18@9909.53,7482.03 ; 9895.54,7493.7 ccw(c9895.54,7519.48) J4.E18@9913.77,7501.25 ; J4.E18@9899.26,7498.9 cw(c9892.7,7500.44) 9892.7,7493.7 ; J4.E18@9899.29,7488.5 ccw(c9892.7,7486.93) 9892.7,7493.7
PXI_C/BE2#: J4.E11 U16.13 | length 667.9
  TopLayer w6: U16.13@9500,7156.22 9678.78,7156.22 9844,6991 9872.84,6991 J4.E11@9921.26,6942.58 ; U16.13@9535.63,7154.44 cw(c9539.92,7150.16) 9539.92,7156.22 cw(c9539.92,7162.28) U16.13@9535.63,7158 ; J4.E11@9898.67,6942.58 ccw(c9844.13,6942.58) 9882.7,6981.15 ccw(c9921.26,7019.71) J4.E11@9921.26,6965.17 ; J4.E11@9904.67,6942.58 ccw(c9864.62,6942.58) 9892.94,6970.9 ccw(c9921.26,6999.23) J4.E11@9921.26,6959.17
PXI_C/BE3#: J4.A9 U16.9 | length 1015.4
  TopLayer w6: U16.9@9500,7077.48 9581.52,7077.48 9834,6825 10196.32,6825 J4.A9@10236.22,6785.1 ; U16.9@9535.63,7075.7 cw(c9539.92,7071.42) 9539.92,7077.48 cw(c9539.92,7083.54) U16.9@9535.63,7079.26 ; J4.A9@10213.63,6785.1 ccw(c10159.09,6785.1) 10197.66,6823.67 ccw(c10236.22,6862.23) J4.A9@10236.22,6807.69 ; J4.A9@10219.63,6785.1 ccw(c10179.58,6785.1) 10207.9,6813.42 ccw(c10236.22,6841.75) J4.A9@10236.22,6801.69
PXI_CLK10: J5.E17 R60.1 | length 1178.6
  TopLayer w8: R60.1@9625.46,8690 9665,8690 ; R60.1@9638.59,8678.97 cw(c9665,8652.86) 9665,8690 ; R60.1@9638.59,8701.03 ccw(c9665,8727.14) 9665,8690 ; J5.E17@9899.67,9383.53 ccw(c9847.55,9383.53) 9884.4,9420.39 ccw(c9921.26,9457.24) J5.E17@9921.26,9405.12 ; J5.E17@9907.67,9383.53 ccw(c9874.86,9383.53) 9898.06,9406.73 ccw(c9921.26,9429.93) J5.E17@9921.26,9397.12 ; J5.E17@9921.26,9383.53 9879.79,9425 9770,9425 9704,9359 9704,8729 9665,8690
PXI_DEVSEL#: J4.A16 U16.18 | length 928.1
  TopLayer w6: U16.18@9500,7254.65 9722.65,7254.65 9765,7297 10196.94,7297 J4.A16@10236.22,7336.28 ; U16.18@9535.63,7252.87 cw(c9539.92,7248.58) 9539.92,7254.65 cw(c9539.92,7260.71) U16.18@9535.63,7256.42 ; J4.A16@10213.63,7336.28 cw(c10159.09,7336.28) 10197.66,7297.72 cw(c10236.22,7259.15) J4.A16@10236.22,7313.69 ; J4.A16@10219.63,7336.28 cw(c10179.58,7336.28) 10207.9,7307.96 cw(c10236.22,7279.64) J4.A16@10236.22,7319.69
PXI_ENUM#: J4.C25
PXI_FRAME#: J4.B15 U20.10 | length 850.5
  BottomLayer w6: U20.10@9500,7222.84 9724.17,7222.84 9749,7198 10097.94,7198 J4.B15@10157.48,7257.54 ; U20.10@9535.63,7221.06 cw(c9539.92,7216.77) 9539.92,7222.84 cw(c9539.92,7228.9) U20.10@9535.63,7224.61 ; J4.B15@10134.89,7257.54 cw(c10080.35,7257.54) 10118.92,7218.98 cw(c10157.48,7180.41) J4.B15@10157.48,7234.95 ; J4.B15@10140.89,7257.54 cw(c10100.84,7257.54) 10129.16,7229.22 cw(c10157.48,7200.9) J4.B15@10157.48,7240.95
PXI_GNT#: J4.E5 U20.22 | length 1046.4
  BottomLayer w6: U20.22@9500,6986.61 9573.39,6986.61 9606,6954 9606,6667 9752,6521 9850,6521 9900.86,6470.14 J4.E5@9921.26,6470.14 ; U20.22@9535.63,6984.84 cw(c9539.92,6980.55) 9539.92,6986.62 cw(c9539.92,6992.68) U20.22@9535.63,6988.39 ; 9860.2,6510.8 ccw(c9906.72,6557.32) J4.E5@9917.54,6492.42 ; 9868.45,6502.55 ccw(c9909.08,6543.19) J4.E5@9918.53,6486.51 ; 9876.69,6494.31 ccw(c9911.44,6529.06) J4.E5@9919.52,6480.59 ; 9884.93,6486.07 ccw(c9913.79,6514.93) J4.E5@9920.5,6474.67 ; 9893.18,6477.82 ccw(c9916.15,6500.8) J4.E5@9921.49,6468.75
PXI_IDSEL: J4.B9 U20.16 | length 1089.3
  BottomLayer w6: U20.16@9500,7104.73 9610.27,7104.73 9699,7016 9699,6830 9783,6746 10118.38,6746 J4.B9@10157.48,6785.1 ; U20.16@9535.63,7102.95 cw(c9539.92,7098.66) 9539.92,7104.73 cw(c9539.92,7110.79) U20.16@9535.63,7106.5 ; J4.B9@10134.89,6785.1 cw(c10080.35,6785.1) 10118.92,6746.54 cw(c10157.48,6707.97) J4.B9@10157.48,6762.51 ; J4.B9@10140.89,6785.1 cw(c10100.84,6785.1) 10129.16,6756.78 cw(c10157.48,6728.46) J4.B9@10157.48,6768.51
PXI_INTA#: J4.A3 U20.24 | length 1330
  BottomLayer w6: U20.24@9500,6947.24 9558.75,6947.24 9571,6935 9571,6640 9858,6353 10195.88,6353 J4.A3@10236.22,6312.66 ; U20.24@9535.63,6945.47 cw(c9539.92,6941.18) 9539.92,6947.24 cw(c9539.92,6953.31) U20.24@9535.63,6949.02 ; J4.A3@10213.63,6312.66 ccw(c10159.09,6312.66) 10197.66,6351.23 ccw(c10236.22,6389.79) J4.A3@10236.22,6335.25 ; J4.A3@10219.63,6312.66 ccw(c10179.58,6312.66) 10207.9,6340.98 ccw(c10236.22,6369.3) J4.A3@10236.22,6329.25
PXI_INTB#: J4.B3
PXI_INTC#: J4.C3
PXI_INTD#: J4.E3
PXI_INTP: J4.D4
PXI_INTS: J4.E4
PXI_IPMB_PWR: J4.A4
PXI_IPMB_SCL: J4.B17
PXI_IPMB_SDA: J4.C17
PXI_IRDY#: J4.C15 U16.16 | length 754.4
  TopLayer w6: U16.16@9500,7215.27 10036.47,7215.27 J4.C15@10078.74,7257.54 ; U16.16@9535.63,7213.5 cw(c9539.92,7209.21) 9539.92,7215.28 cw(c9539.92,7221.34) U16.16@9535.63,7217.05 ; J4.C15@10056.15,7257.54 cw(c10001.61,7257.54) 10040.18,7218.98 cw(c10078.74,7180.41) J4.C15@10078.74,7234.95 ; J4.C15@10062.15,7257.54 cw(c10022.1,7257.54) 10050.42,7229.22 cw(c10078.74,7200.9) J4.C15@10078.74,7240.95
PXI_LOCK#: J4.E16
PXI_PAR: J4.D18 U20.7 | length 899.9
  BottomLayer w6: U20.7@9500,7281.89 9730.89,7281.89 9748,7299 10013,7299 10039,7325 10039,7454.76 J4.D18@10000,7493.76 ; U20.7@9535.63,7280.11 cw(c9539.92,7275.83) 9539.92,7281.89 cw(c9539.92,7287.95) U20.7@9535.63,7283.67 ; J4.D18@10000,7471.17 cw(c10000,7416.64) 10038.56,7455.2 cw(c10077.13,7493.76) J4.D18@10022.59,7493.76 ; J4.D18@10000,7477.17 cw(c10000,7437.12) 10028.32,7465.44 cw(c10056.64,7493.76) J4.D18@10016.59,7493.76
PXI_PCLK: J4.D6 U16.2 | length 1665.6
  TopLayer w6: U16.2@9500,6939.69 9544.32,6939.69 9551,6933 9551.15,6597.98 ccw(c9564,6596) 9577,6596 9577,6911 cw(c9588,6910) 9599.05,6910 ; U16.2@9535.63,6937.91 cw(c9539.92,6933.62) 9539.92,6939.69 cw(c9539.92,6945.75) U16.2@9535.63,6941.46 ; 9599,6910 9599,6665 9755,6509 9960.12,6509 J4.D6@10000,6548.88 ; J4.D6@9977.41,6548.88 cw(c9922.87,6548.88) 9961.44,6510.32 cw(c10000,6471.75) J4.D6@10000,6526.29 ; J4.D6@9983.41,6548.88 cw(c9943.36,6548.88) 9971.68,6520.56 cw(c10000,6492.24) J4.D6@10000,6532.29
PXI_PERR#: J4.E17 U16.19 | length 637.6
  TopLayer w6: U16.19@9500,7274.33 9710.33,7274.33 9754,7318 9824.24,7318 J4.E17@9921.26,7415.02 ; U16.19@9535.63,7272.55 cw(c9539.92,7268.27) 9539.92,7274.33 cw(c9539.92,7280.39) U16.19@9535.63,7276.11 ; J4.E17@9898.67,7415.02 cw(c9844.13,7415.02) 9882.7,7376.46 cw(c9921.26,7337.9) J4.E17@9921.26,7392.43 ; J4.E17@9904.67,7415.02 cw(c9864.62,7415.02) 9892.94,7386.7 cw(c9921.26,7358.38) J4.E17@9921.26,7398.43
PXI_REQ64#: J4.B25
PXI_REQ#: J4.A6 U16.3 | length 1203.2
  TopLayer w6: U16.3@9500,6959.37 9572.63,6959.37 9612,6920 9612,6683 9706,6589 10196.1,6589 J4.A6@10236.22,6548.88 ; U16.3@9535.63,6957.59 cw(c9539.92,6953.31) 9539.92,6959.37 cw(c9539.92,6965.43) U16.3@9535.63,6961.15 ; J4.A6@10213.63,6548.88 ccw(c10159.09,6548.88) 10197.66,6587.45 ccw(c10236.22,6626.01) J4.A6@10236.22,6571.47 ; J4.A6@10219.63,6548.88 ccw(c10179.58,6548.88) 10207.9,6577.2 ccw(c10236.22,6605.53) J4.A6@10236.22,6565.47
PXI_RST#: J4.C5 U20.23 | length 1144
  BottomLayer w6: U20.23@9500,6966.93 9570.07,6966.93 9590,6947 9590,6653 9811,6432 10040.6,6432 ; U20.23@9535.63,6965.15 cw(c9539.92,6960.87) 9539.92,6966.93 cw(c9539.92,6972.99) U20.23@9535.63,6968.71 ; J4.C5@10056.15,6469.96 cw(c10003.06,6469.55) 10040.6,6432 ; J4.C5@10062.15,6470.01 cw(c10023.16,6469.7) 10050.73,6442.13 cw(c10078.3,6414.56) J4.C5@10078.61,6453.55 ; J4.C5@10078.56,6447.55 ccw(c10078.14,6394.46) 10040.6,6432 ; J4.C5@10078.74,6470.14 10040.6,6432
PXI_SERR#: J4.A18 U16.20 | length 977.1
  TopLayer w6: U16.20@9500,7294.02 9613.01,7294.02 9771,7452 10194.46,7452 J4.A18@10236.22,7493.76 ; U16.20@9535.63,7292.24 cw(c9539.92,7287.95) 9539.92,7294.02 cw(c9539.92,7300.08) U16.20@9535.63,7295.79 ; J4.A18@10213.63,7493.76 cw(c10159.09,7493.76) 10197.66,7455.2 cw(c10236.22,7416.64) J4.A18@10236.22,7471.17 ; J4.A18@10219.63,7493.76 cw(c10179.58,7493.76) 10207.9,7465.44 cw(c10236.22,7437.12) J4.A18@10236.22,7477.17
PXI_START: J5.D17 R86.2 | length 1626.9
  BottomLayer w8: 9148.4,8720.14 cw(c9118.26,8690) R86.2@9160.88,8690 ; 9153.15,8715.38 ccw(c9176.57,8738.8) R86.2@9176.57,8705.68 ; R86.2@9162.06,8706.48 cw(c9145.58,8690) R86.2@9168.88,8690 ; R86.2@9178.54,8690 9111,8757.54 9111,8916 9172,8977 9595,8977 9728,9110 9728,9248 9827,9347 9963.47,9347 ; J5.D17@9978.41,9383.39 cw(c9927.41,9383.06) 9963.47,9347 ; J5.D17@9986.41,9383.44 cw(c9954.31,9383.24) 9977.01,9360.54 cw(c9999.71,9337.84) J5.D17@9999.91,9369.94 ; J5.D17@9999.86,9361.94 ccw(c9999.53,9310.94) 9963.47,9347 ; J5.D17@10000,9383.53 9963.47,9347
PXI_STOP#: J4.D16 U20.6 | length 706.2
  BottomLayer w6: U20.6@9500,7301.57 9719.58,7301.57 9740.03,7322.03 9840.03,7322.03 9895,7377 9959.28,7377 J4.D16@10000,7336.28 ; U20.6@9535.63,7299.8 cw(c9539.92,7295.51) 9539.92,7301.58 cw(c9539.92,7307.64) U20.6@9535.63,7303.35 ; J4.D16@9977.41,7336.28 ccw(c9922.87,7336.28) 9961.44,7374.85 ccw(c10000,7413.41) J4.D16@10000,7358.87 ; J4.D16@9983.41,7336.28 ccw(c9943.36,7336.28) 9971.68,7364.61 ccw(c10000,7392.93) J4.D16@10000,7352.87
PXI_TCK: J4.A2
PXI_TDIO: J4.D2 J4.E2 | length 393.8
  BottomLayer w6: J4.E2@9925.89,6234.78 J4.D2@10000,6233.92 ; J4.E2@9928.66,6226.35 cw(c9948.7,6205.83) 9949.04,6234.51 ; J4.E2@9932.85,6222.05 cw(c9963.02,6191.18) 9963.52,6234.34 ; J4.E2@9933.13,6245.52 ccw(c9959.55,6271.33) 9959.12,6234.39 ; J4.E2@9937.05,6217.76 cw(c9977.34,6176.53) J4.D2@9978,6234.18 ; J4.E2@9937.42,6249.71 ccw(c9974.2,6285.65) 9973.6,6234.23 ; J4.D2@9983.84,6218.13 ccw(c9944.83,6180.02) 9945.47,6234.55 ccw(c9946.1,6289.09) J4.D2@9984.21,6250.08 ; J4.D2@9988.13,6222.33 ccw(c9959.49,6194.33) 9959.95,6234.38 ccw(c9960.41,6274.43) J4.D2@9988.41,6245.79
PXI_TMS: J4.C2
PXI_TRDY#: J4.E15 U20.9 | length 610
  BottomLayer w6: U20.9@9500,7242.52 9732.48,7242.52 9762,7213 9876.72,7213 J4.E15@9921.26,7257.54 ; U20.9@9535.63,7240.74 cw(c9539.92,7236.46) 9539.92,7242.52 cw(c9539.92,7248.58) U20.9@9535.63,7244.3 ; J4.E15@9898.67,7257.54 cw(c9844.13,7257.54) 9882.7,7218.98 cw(c9921.26,7180.41) J4.E15@9921.26,7234.95 ; J4.E15@9904.67,7257.54 cw(c9864.62,7257.54) 9892.94,7229.22 cw(c9921.26,7200.9) J4.E15@9921.26,7240.95
PXI_TRIG0: J5.B16 R58.1 | length 1456.1
  TopLayer w8: R58.1@9625.46,8490 9667,8490 9744,8567 9744,9239 9770,9265 10117.69,9265 J5.B16@10157.48,9304.79 ; R58.1@9638.52,8478.91 cw(c9665.3,8452.13) 9665.3,8490 cw(c9665.3,8527.87) R58.1@9638.52,8501.09 ; J5.B16@10135.89,9304.79 cw(c10083.77,9304.79) 10120.62,9267.93 cw(c10157.48,9231.07) J5.B16@10157.48,9283.2 ; J5.B16@10143.89,9304.79 cw(c10111.08,9304.79) 10134.28,9281.59 cw(c10157.48,9258.39) J5.B16@10157.48,9291.2
PXI_TRIG1: J5.A16 R85.2 | length 1530.3
  BottomLayer w8: R85.2@9167.51,8901.16 ccw(c9141.47,8927.53) 9178.54,8927.53 ; R85.2@9178.54,8890 9178.54,8927.54 ; R85.2@9189.56,8901.16 cw(c9215.6,8927.53) 9178.54,8927.53 ; J5.A16@10214.63,9304.79 cw(c10162.51,9304.79) 10199.36,9267.93 cw(c10236.22,9231.07) J5.A16@10236.22,9283.2 ; J5.A16@10222.63,9304.79 cw(c10189.82,9304.79) 10213.02,9281.59 cw(c10236.22,9258.39) J5.A16@10236.22,9291.2 ; J5.A16@10236.22,9304.79 10197.43,9266 9810,9266 9776,9232 9776,9084 9634,8942 9193,8942 9178.54,8927.54
PXI_TRIG2: J5.A17 R59.1 | length 1471.1
  TopLayer w8: R59.1@9625.46,8590 9661,8590 ; R59.1@9639.46,8579.94 cw(c9661,8561.93) 9661,8590 ; R59.1@9639.46,8600.06 ccw(c9661,8618.07) 9661,8590 ; J5.A17@10214.63,9383.53 cw(c10162.51,9383.53) 10199.36,9346.67 cw(c10236.22,9309.81) J5.A17@10236.22,9361.94 ; J5.A17@10222.63,9383.53 cw(c10189.82,9383.53) 10213.02,9360.33 cw(c10236.22,9337.13) J5.A17@10236.22,9369.94 ; J5.A17@10236.22,9383.53 10197.69,9345 9820,9345 9724,9249 9724,8653 9661,8590
PXI_TRIG3: J5.A18 R84.2 | length 2058.1
  BottomLayer w8: 9148.4,8620.14 cw(c9118.26,8590) R84.2@9160.88,8590 ; 9153.15,8615.38 ccw(c9176.57,8638.8) R84.2@9176.57,8605.68 ; R84.2@9162.06,8606.48 cw(c9145.58,8590) R84.2@9168.88,8590 ; R84.2@9178.54,8590 9093,8675.54 9093,8921 9165,8993 9579,8993 9708,9122 9708,9257 9778,9327 9778,9385 9815,9422 10195.95,9422 J5.A18@10236.22,9462.27 ; J5.A18@10214.63,9462.27 cw(c10162.51,9462.27) 10199.36,9425.41 cw(c10236.22,9388.55) J5.A18@10236.22,9440.68 ; J5.A18@10222.63,9462.27 cw(c10189.82,9462.27) 10213.02,9439.07 cw(c10236.22,9415.87) J5.A18@10236.22,9448.68
PXI_TRIG4: J5.B18 R62.1 | length 1316.4
  TopLayer w8: R62.1@9625.46,8890 9649,8890 ; R62.1@9627.28,8889.73 ccw(c9637.47,8907.76) 9652.11,8893.11 ; R62.1@9631.21,8896.69 ccw(c9642.84,8917.27) 9659.56,8900.56 ; R62.1@9635.15,8903.66 ccw(c9648.22,8926.78) 9667,8908 ; R62.1@9642.36,8885.17 cw(c9649,8883.02) 9649,8890 ; R62.1@9642.36,8894.83 ccw(c9649,8896.98) 9649,8890 ; J5.B18@10135.89,9462.27 ccw(c10083.77,9462.27) 10120.62,9499.13 ccw(c10157.48,9535.98) J5.B18@10157.48,9483.86 ; J5.B18@10143.89,9462.27 ccw(c10111.08,9462.27) 10134.28,9485.47 ccw(c10157.48,9508.67) J5.B18@10157.48,9475.86 ; J5.B18@10157.48,9462.27 10119.75,9500 9793,9500 9667,9374 9667,8908 ; 9649,8890 9667,8908
PXI_TRIG5: J5.C18 R83.2 | length 2061
  BottomLayer w8: 9148.4,8520.14 cw(c9118.26,8490) R83.2@9160.88,8490 ; 9153.15,8515.38 ccw(c9176.57,8538.8) R83.2@9176.57,8505.68 ; R83.2@9162.06,8506.48 cw(c9145.58,8490) R83.2@9168.88,8490 ; R83.2@9178.54,8490 9074,8594.54 9074,8926 9157,9009 9560,9009 9683,9132 9683,9262 9754,9333 9754,9392 9864,9502 10039.01,9502 J5.C18@10078.74,9462.27 ; J5.C18@10057.15,9462.27 ccw(c10005.03,9462.27) 10041.88,9499.13 ccw(c10078.74,9535.98) J5.C18@10078.74,9483.86 ; J5.C18@10065.15,9462.27 ccw(c10032.34,9462.27) 10055.54,9485.47 ccw(c10078.74,9508.67) J5.C18@10078.74,9475.86
PXI_TRIG6: J5.E18 R61.1 | length 1070.3
  TopLayer w8: R61.1@9625.46,8790 9658,8790 ; R61.1@9640.18,8780.85 cw(c9658,8768.06) 9658,8790 ; R61.1@9640.18,8799.15 ccw(c9658,8811.94) 9658,8790 ; J5.E18@9905.99,9447 ccw(c9869.14,9410.14) 9869.14,9462.27 ccw(c9869.14,9514.39) J5.E18@9905.99,9477.53 ; J5.E18@9911.65,9452.66 ccw(c9888.45,9429.46) 9888.45,9462.27 ccw(c9888.45,9495.08) J5.E18@9911.65,9471.88 ; J5.E18@9921.26,9462.27 9782.27,9462.27 9686,9366 9686,8818 9658,8790
PXI_TRIG7: J5.E16 R87.2 | length 1393.4
  BottomLayer w8: 9148.4,8820.14 cw(c9118.26,8790) R87.2@9160.88,8790 ; 9153.15,8815.38 ccw(c9176.57,8838.8) R87.2@9176.57,8805.68 ; R87.2@9162.06,8806.48 cw(c9145.58,8790) R87.2@9168.88,8790 ; R87.2@9178.54,8790 9130,8838.54 9130,8911 9178,8959 9621,8959 9753,9091 9753,9239 9818.79,9304.79 J5.E16@9921.26,9304.79 ; J5.E16@9905.99,9289.52 ccw(c9869.14,9252.66) 9869.14,9304.79 ccw(c9869.14,9356.91) J5.E16@9905.99,9320.05 ; J5.E16@9911.65,9295.18 ccw(c9888.45,9271.98) 9888.45,9304.79 ccw(c9888.45,9337.6) J5.E16@9911.65,9314.4
PXI_TRST#: J4.C1
PXI_VIO: J4.C4 pad.2@9345,6353 | length 915
  TopLayer w12: pad.2@9345,6353 10040.34,6353 J4.C4@10078.74,6391.4 ; pad.2@9361.97,6336.03 cw(c9402.94,6295.06) 9402.94,6353 cw(c9402.94,6410.94) pad.2@9361.97,6369.97 ; J4.C4@10059.15,6391.4 cw(c10011.85,6391.4) 10045.3,6357.96 cw(c10078.74,6324.52) J4.C4@10078.74,6371.81
SCL: R76.2 U11.E4 | length 3520.3
  TopLayer w6: U11.E4@8847.89,6985.23 cw(c8847.89,6970.14) 8858.56,6980.81 cw(c8869.24,6991.48) U11.E4@8854.14,6991.48 ; U11.E4@8847.89,6991.48 v1(8866.37,6973) ; v1(8868,6777) v1(9199,6777) ; v1@8871.54,6773.46 cw(c8880.07,6764.93) 8880.07,6777 cw(c8880.07,6789.07) v1@8871.54,6780.54 ; v1@9195.46,6773.46 ccw(c9186.93,6764.93) 9186.93,6777 ccw(c9186.93,6789.07) v1@9195.46,6780.54
  BottomLayer w6: R76.2@7773.46,8160 8552.03,8160 8695.03,8017 9265,8017 9322,7960 9322,6900 v1(9199,6777) ; v1@8864.44,6780.51 ccw(c8855.83,6788.97) 8867.9,6789.07 ccw(c8879.97,6789.17) v1@8871.51,6780.56 ; v1@8866.37,6778.63 v1(8868,6777) v1(8866.37,6973) ; v1@9199,6782 ccw(c9199,6794.07) 9207.54,6785.54 ccw(c9216.07,6777) v1@9204,6777
SDA: R77.2 U11.D3 | length 3172.6
  TopLayer w6: U11.D3@8887.26,6945.86 cw(c8887.26,6930.77) 8897.93,6941.44 cw(c8908.61,6952.11) U11.D3@8893.51,6952.11 ; U11.D3@8887.26,6952.11 8907.37,6932 v1(9033,6932) ; v1@9029.46,6928.46 ccw(c9020.93,6919.93) 9020.93,6932 ccw(c9020.93,6944.07) v1@9029.46,6935.54
  BottomLayer w6: R77.2@7773.46,8040 7858.46,8125 8565,8125 8686,8004 9250,8004 9304,7950 9304,6928 9275,6899 9066,6899 v1(9033,6932) ; v1@9033,6927 cw(c9033,6914.93) 9041.54,6923.46 cw(c9050.07,6932) v1@9038,6932
SDCKE: R34.6 U4.67 | length 1886.9
  TopLayer w6: v1(6646,7113) R34.6@7555.84,7113 ; v1@6649.54,7109.46 cw(c6658.07,7100.93) 6658.07,7113 cw(c6658.07,7125.07) v1@6649.54,7116.54 ; v1@6728.45,6434.45 cw(c6719.91,6425.91) 6731.98,6425.91 cw(c6744.06,6425.91) v1@6735.52,6434.45 ; U4.67@6729.93,6399.52 ccw(c6724.97,6404.48) 6731.99,6404.48 ccw(c6739,6404.48) U4.67@6734.04,6399.52 ; U4.67@6731.98,6364 v1(6731.98,6437.98) ; R34.6@7543.1,7108.76 ccw(c7532.86,7098.51) 7532.86,7113 ccw(c7532.86,7127.49) R34.6@7543.1,7117.24
  BottomLayer w6: v1@6641,7113 cw(c6628.93,7113) 6637.46,7104.46 cw(c6646,7095.93) v1@6646,7108 ; v1(6646,7113) 6546,7013 6546,6896 6731.98,6710.02 v1(6731.98,6437.98) ; v1@6728.45,6441.52 ccw(c6719.91,6450.06) 6731.98,6450.06 ccw(c6744.06,6450.06) v1@6735.52,6441.52
SYSTEM_RESET#: R30.1 U1.17 U8.1 U11.P4 | length 6994.4
  TopLayer w6: U1.17@6274.31,7988.25 6336.75,7988.25 6702,7623 7014,7623 7109,7718 7556,7718 7588,7750 7588,7896 7510.54,7973.46 R30.1@7400,7973.46 7386.54,7960 U8.1@7300,7960 ; U1.17@6312.78,7986.2 cw(c6317.74,7981.24) 6317.74,7988.25 cw(c6317.74,7995.27) U1.17@6312.78,7990.31 ; U8.1@7306.23,7953.77 cw(c7321.27,7938.73) 7321.27,7960 cw(c7321.27,7981.27) U8.1@7306.23,7966.23 ; 7331.96,7960 ccw(c7331.96,8039.53) R30.1@7388.2,7983.29 ; 7346.45,7960 ccw(c7346.45,8025.05) R30.1@7392.44,7979.05 ; 7360.94,7960 ccw(c7360.94,8010.56) R30.1@7396.69,7974.81 ; 7375.42,7960 ccw(c7375.42,7996.08) R30.1@7400.93,7970.57 ; R30.1@7400,7974.12 ccw(c7400,8010.62) 7425.81,7984.81 ; R30.1@7400,7980.12 ccw(c7400,8031.1) 7436.05,7995.05 ; R30.1@7400,7986.12 ccw(c7400,8051.59) 7446.29,8005.29 ; R30.1@7400,7992.12 ccw(c7400,8072.07) 7456.54,8015.54 ; R30.1@7407.56,7965.91 cw(c7425.8,7947.67) 7425.8,7973.46 cw(c7425.8,7999.26) R30.1@7407.56,7981.02 ; R30.1@7411.8,7961.67 cw(c7440.28,7933.18) 7440.28,7973.46 cw(c7440.28,8013.75) R30.1@7411.8,7985.26 ; R30.1@7414.46,7973.46 7661,8220 v1(7830,8220) ; v1(8829,7326.92) U11.P4@8847.89,7345.81 ; U11.P4@8841.64,7345.81 cw(c8826.54,7345.81) 8837.22,7335.14 cw(c8847.89,7324.47) U11.P4@8847.89,7339.56 ; v1(8868,6747) 9211,6747 v1(9211,6748) ; v1@8871.54,6743.46 cw(c8880.07,6734.93) 8880.07,6747 cw(c8880.07,6759.07) v1@8871.54,6750.54 ; 9196.51,6747 ccw(c9196.51,6762.49) v1@9207.46,6751.54 ; 9201.34,6747 cw(c9201.34,6738.34) v1@9207.46,6744.46
  BottomLayer w6: v1(7830,8220) 8509,8220 8700,8029 9279,8029 9342,7966 9342,6879 v1(9211,6748) ; v1@7833.54,8216.46 cw(c7842.07,8207.93) 7842.07,8220 cw(c7842.07,8232.07) v1@7833.54,8223.54 ; v1(8829,7326.92) 8847,7308.92 8847,6768 v1(8868,6747) ; v1@8863,6747 ccw(c8850.93,6747) 8859.46,6755.54 ccw(c8868,6764.07) v1@8868,6752 ; v1@9211,6753 ccw(c9211,6765.07) 9219.54,6756.54 ccw(c9228.07,6748) v1@9216,6748
TTLIN1: DL2.15 R96.2 U1.162 | length 437
  TopLayer w10: R96.2@4560,8126.54 4696.44,7990.1 DL2.15@4759.3,7990.1 4815.1,7990.1 4852.62,8027.62 U1.162@4924.9,8027.62
TTLIN2: DL2.14 U1.163 | length 193.7
  TopLayer w10: DL2.14@4759.3,7940.1 4815.1,7940.1 4882.94,8007.94 U1.163@4924.9,8007.94
TTLIN3: DL2.11 U1.173 | length 174.3
  TopLayer w10: DL2.11@4759.3,7790.1 4833.1,7790.1 4854.09,7811.09 U1.173@4924.9,7811.09
TTLIN4: DL2.10 U1.174 | length 186.8
  TopLayer w10: DL2.10@4759.3,7740.1 4820.1,7740.1 4871.4,7791.4 U1.174@4924.9,7791.4
TTLOUT1: DL1.2 U1.140 | length 314
  TopLayer w10: v3(4693,8428) 4814,8428 4846.69,8460.69 U1.140@4924.9,8460.69
  BottomLayer w10: v3(4693,8428) 4695.1,8430.1 DL1.2@4760.7,8430.1
TTLOUT2: DL1.3 U1.141 | length 322.8
  TopLayer w10: v3(4694,8381) 4813,8381 4873.01,8441.01 U1.141@4924.9,8441.01
  BottomLayer w10: v3(4694,8381) 4759.8,8381 DL1.3@4760.7,8380.1
TTLOUT3: DL1.6 U1.159 | length 373.5
  TopLayer w10: v3(4701,8230) 4767,8230 4836,8161 4836,8109 4858.32,8086.68 U1.159@4924.9,8086.68
  BottomLayer w10: v3(4701,8230) 4701.1,8230.1 DL1.6@4760.7,8230.1
TTLOUT4: DL1.7 U1.160 | length 361.4
  TopLayer w10: v3(4699,8180) 4783,8180 4815,8148 4815,8102 4850.01,8066.99 U1.160@4924.9,8066.99
  BottomLayer w10: v3(4699,8180) 4699.1,8180.1 DL1.7@4760.7,8180.1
